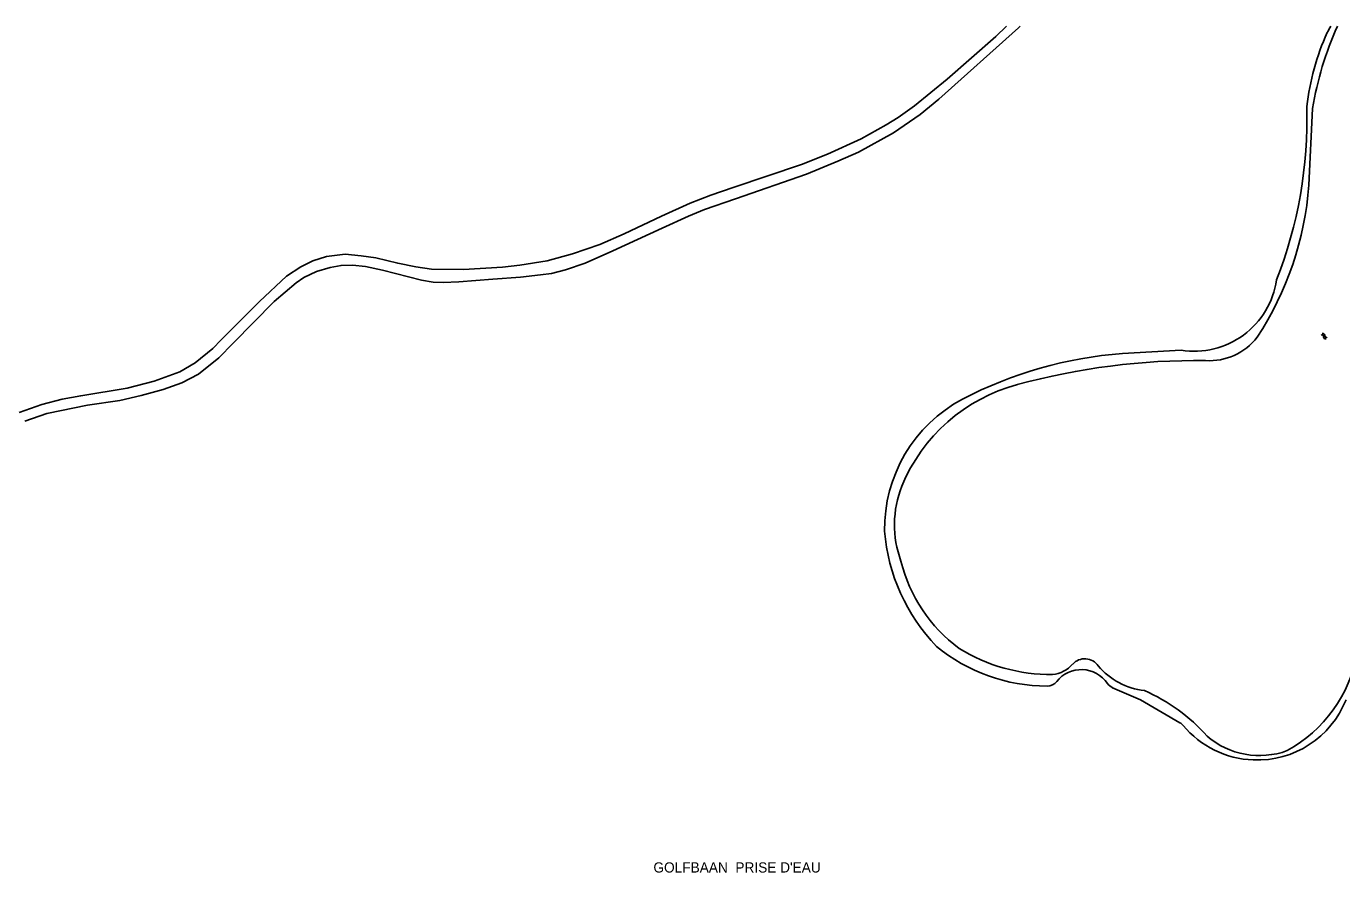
# Model space of a CAD drawing. Extents: x 126000 to 131009, y 393000 to 395500.
# Drawn here: x 127157.3 to 127479.3, y 395292.8 to 395500 of the extents above; entities that cross this region are included whole.
import ezdxf

# ---------------------------------------------------------------- set-up
doc = ezdxf.new("R2010")
doc.units = 0
for name, color, linetype in [('gg-knt-onverhard', 7, 'Continuous'), ('gg-kntw-bovenkant insteek waterloop', 7, 'Continuous'), ('gg-kntw-waterlijn', 7, 'Continuous'), ('gt-anno-overige text', 7, 'Continuous'), ('gt-symb-watersymbool', 7, 'Continuous')]:
    doc.layers.add(name, color=color, linetype=linetype)

# ---------------------------------------------------------------- blocks, each defined once
blk = doc.blocks.new('gt0-WA')
at = {"layer": 'gt-symb-watersymbool'}
for centre, start, end in [((-0.32, 0.02), 28.0725, 151.9275), ((0.43, 0.42), 208.0725, 331.9275), ((-0.32, -0.43), 28.0725, 151.9275), ((0.43, -0.03), 208.0725, 331.9275)]:
    blk.add_arc(centre, 0.425, start, end, dxfattribs=at)

msp = doc.modelspace()

# ---------------------------------------------------------------- linework, layer by layer
at = {"layer": 'gg-knt-onverhard'}
for points in [[(127397.22, 395500), (127394.68, 395497.5), (127382.71, 395487.08), (127374.74, 395480.5), (127370.75, 395477.67), (127367.78, 395475.86), (127361.7, 395472.45), (127353.48, 395468.7), (127347.06, 395466.17), (127330.35, 395460.52), (127324.85, 395458.62), (127319.84, 395456.67), (127312.83, 395453.51), (127303.69, 395449.23), (127297.69, 395446.58), (127291.03, 395444.3), (127284.8, 395442.59), (127278.13, 395441.52), (127273.92, 395441.01), (127264.33, 395440.46), (127256.54, 395440.55), (127252.68, 395441.11), (127248.23, 395442), (127242.89, 395443.29), (127239.25, 395443.84), (127235.41, 395444.18), (127230.76, 395443.64), (127227.45, 395442.56), (127224.5, 395441.14), (127221.03, 395438.83), (127214.39, 395432.64), (127205.05, 395423.22), (127202.97, 395421.14), (127198.65, 395417.58), (127194.87, 395415.41), (127188.64, 395413.1), (127181.99, 395411.41), (127170.64, 395409.54), (127166.08, 395408.71), (127161.08, 395407.37), (127155.55, 395405.43)], [(127156.99, 395403.29), (127162.32, 395405.18), (127172.33, 395407.21), (127180.17, 395408.4), (127185.45, 395409.63), (127190.79, 395411.08), (127195.41, 395412.69), (127199.46, 395414.84), (127204.46, 395418.87), (127207.99, 395422.4), (127217.97, 395432.59), (127223.37, 395437.17), (127225.27, 395438.53), (127228.38, 395439.99), (127231.68, 395440.97), (127234.35, 395441.47), (127237.19, 395441.53), (127240.33, 395441.22), (127244.5, 395440.27), (127254.08, 395437.88), (127256.89, 395437.38), (127259.39, 395437.27), (127263.23, 395437.41), (127271.5, 395438.07), (127278.26, 395438.62), (127283.18, 395439.13), (127285.9, 395439.52), (127289.27, 395440.37), (127294.14, 395442.02), (127300.9, 395444.99), (127312.97, 395450.54), (127319.44, 395453.55), (127323.36, 395455.17), (127330.95, 395457.75), (127348.33, 395463.77), (127355.95, 395467), (127361.01, 395469.17), (127369.58, 395473.92), (127376.09, 395478.4), (127380.73, 395482.18), (127400.22, 395499.64), (127400.62, 395500)]]:
    msp.add_lwpolyline(points, dxfattribs=at)
at = {"layer": 'gg-kntw-bovenkant insteek waterloop'}
for p, q in [((127440, 395420.72), (127425.66, 395419.92)), ((127430.1, 395335.13), (127423.24, 395338.07)), ((127439.7, 395329.5), (127430.1, 395335.13))]:
    msp.add_line(p, q, dxfattribs=at)
for centre, radius, start, end in [((127531.76, 395473.26), 61.41, 155.7775, 173.3359), ((127498.67, 395486.03), 26.07, 147.5902, 151.5338), ((127362.4, 395477.35), 108.4, 338.6597, 1.6039), ((127443.25, 395440.78), 20.32, 260.7952, 351.8669), ((127433.41, 395318.68), 101.53, 94.3735, 117.5377), ((127403.48, 395376.9), 36.08, 118.1403, 180.8042), ((127413.44, 395380.2), 46.19, 184.7351, 223.8831), ((127407.33, 395381.27), 42.82, 230.5954, 269.8029), ((127415.58, 395334.79), 7.71, 34.3035, 141.5316), ((127407.19, 395341.45), 3, 269.7838, 321.5645), ((127424.43, 395340.83), 3, 214.3051, 246.7995), ((127458.66, 395343.71), 23.35, 267.5948, 338.4277), ((127438.17, 395326.9), 3.01, 39.905, 59.5569), ((127458.56, 395343.91), 23.54, 219.8211, 267.8433)]:
    msp.add_arc(centre, radius, start, end, dxfattribs=at)
at = {"layer": 'gg-kntw-waterlijn'}
msp.add_line((127472.15, 395479.9), (127471.27, 395461.1), dxfattribs=at)
for centre, radius, start, end in [((127555.99, 395465.41), 85.09, 156.013, 170.1977), ((127393.25, 395466.84), 78.23, 326.6979, 355.7952), ((127446.92, 395432.9), 14.78, 266.3622, 322.385), ((127443.77, 395252.19), 165.98, 89.2363, 105.3222), ((127410.88, 395371.28), 42.43, 104.9772, 157.6364), ((127395.78, 395377.94), 25.94, 158.5544, 200.0617), ((127408.39, 395378.26), 38.11, 193.9952, 233.3416), ((127408.28, 395384.48), 43.2, 238.397, 270.3684), ((127407.63, 395348.99), 7.76, 276.85, 318.6401), ((127416.42, 395341.15), 4.01, 34.7509, 137.6124), ((127449.38, 395352.71), 34.33, 298.9415, 349.5309), ((127432.97, 395354.53), 17.28, 219.9435, 263.5475), ((127413.75, 395297.54), 43.41, 41.3251, 66.5526), ((127459.2, 395341.24), 19.78, 229.4753, 290.086)]:
    msp.add_arc(centre, radius, start, end, dxfattribs=at)

# ---------------------------------------------------------------- block references
at = {"layer": 'gt-symb-watersymbool', "rotation": -36.377067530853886}
msp.add_blockref('gt0-WA', (127474.97, 395424.18), dxfattribs=at)

# ---------------------------------------------------------------- texts
at = {"layer": 'gt-anno-overige text'}
msp.add_text("GOLFBAAN  PRISE D'EAU", height=2.5, dxfattribs=at).set_placement((127310.83, 395292.82))

doc.saveas('drawing.dxf')
